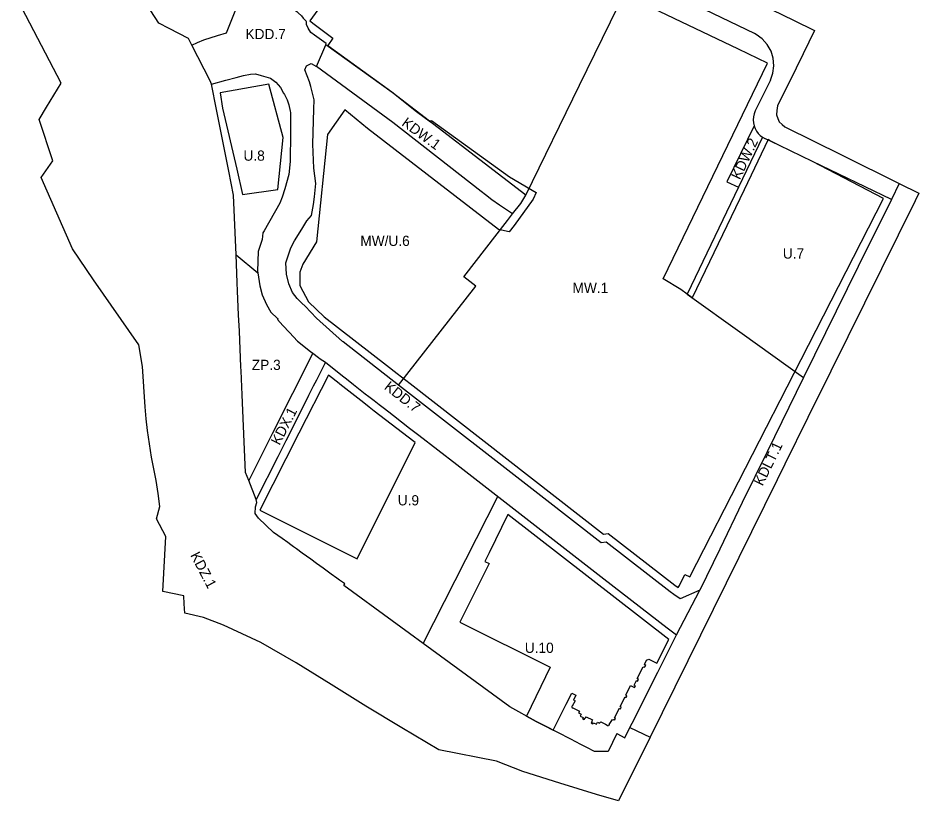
# Model space of a CAD drawing. Extents: x 7424029 to 7425690, y 5548509 to 5549459.
# Drawn here: x 7424711.6 to 7425151.9, y 5548508.9 to 5548891.5 of the extents above; entities that cross this region are included whole.
import ezdxf

# ---------------------------------------------------------------- set-up
doc = ezdxf.new("R2010")
doc.units = 0
for name, color, linetype in [('LIN_Linia Zabudowy Nieprzekraczalna', 7, 'Continuous'), ('LIN_Linia Zabudowy Obowiazujaca', 7, 'Continuous'), ('LIN_Linie_Rozgraniczajace', 7, 'Continuous'), ('TXT_oznaczenia_przeznaczen', 7, 'Continuous')]:
    doc.layers.add(name, color=color, linetype=linetype)

msp = doc.modelspace()

# ---------------------------------------------------------------- linework, layer by layer
at = {"layer": 'LIN_Linia Zabudowy Nieprzekraczalna'}
for p, q in [((7424865.54, 5548881.7), (7424862.95, 5548878.1)), ((7424834.13, 5548859.18), (7424810.38, 5548854.97)), ((7424841.17, 5548833.21), (7424834.13, 5548859.18)), ((7424871.36, 5548846.67), (7424862.85, 5548834.63)), ((7424838.56, 5548807.66), (7424841.17, 5548833.21)), ((7424862.85, 5548834.63), (7424857.5, 5548782.14)), ((7424821.24, 5548805.23), (7424838.56, 5548807.66)), ((7424829.77, 5548650.99), (7424877.39, 5548627.21)), ((7424927.49, 5548596.21), (7424971.61, 5548574.28)), ((7425023.83, 5548576.17), (7425029.71, 5548587.78)), ((7424971.61, 5548574.28), (7424960.06, 5548550.34)), ((7424973.12, 5548543.45), (7424979.54, 5548556.16)), ((7425006.03, 5548541.04), (7425006.03, 5548541.04))]:
    msp.add_line(p, q, dxfattribs=at)
for points in [[(7424926.28, 5548943.21), (7424912, 5548950), (7424898.58, 5548956.55), (7424887.87, 5548961.58), (7424879.12, 5548943.66), (7424883.08, 5548941.73), (7424880.88, 5548937.23), (7424886.34, 5548934.57), (7424866.76, 5548907.56), (7424854.3, 5548890.24)], [(7425077.86, 5548869.45), (7425063.65, 5548876.28), (7425018.21, 5548897.91), (7425017.6, 5548898.24), (7424999.04, 5548907.81), (7424993.69, 5548910.42), (7424976.65, 5548918.72), (7424971.24, 5548921.36), (7424954.74, 5548929.34), (7424949.38, 5548931.95), (7424931.72, 5548940.56), (7424926.28, 5548943.21)], [(7424854.3, 5548890.24), (7424856.99, 5548888.07), (7424865.54, 5548881.7)], [(7424862.95, 5548878.1), (7424894.37, 5548855.5), (7424906.4, 5548845.93), (7424913.17, 5548840.75), (7424913.69, 5548841.47), (7424951.87, 5548813.97), (7424964.88, 5548806.22)], [(7425026.91, 5548764.07), (7425077.86, 5548869.45)], [(7424810.38, 5548854.97), (7424811.62, 5548847.45), (7424818.53, 5548817.61), (7424821.24, 5548805.23)], [(7424951.66, 5548787.1), (7424946.48, 5548788.24), (7424882.45, 5548837.55), (7424871.36, 5548846.67)], [(7425078.22, 5548832.19), (7425066.4, 5548807.61), (7425041.05, 5548754.83)], [(7425134.61, 5548803.32), (7425099.89, 5548821.46), (7425083.71, 5548829.24), (7425078.79, 5548831.68), (7425078.22, 5548832.19)], [(7424964.88, 5548806.22), (7424963.31, 5548802.97), (7424954.08, 5548790.21)], [(7425094.36, 5548724.66), (7425134.61, 5548803.32)], [(7424954.08, 5548790.21), (7424951.66, 5548787.1)], [(7424857.5, 5548782.14), (7424850.76, 5548771.18), (7424849.29, 5548767.37), (7424849.29, 5548760.89), (7424853.5, 5548752.77), (7424861.29, 5548745.48)], [(7425041.05, 5548754.83), (7425038.58, 5548756.61), (7425035.46, 5548758.85), (7425026.91, 5548764.07)], [(7424861.29, 5548745.48), (7424891.62, 5548721.85), (7424896.89, 5548717.74), (7424903.21, 5548712.83)], [(7425034.23, 5548613.25), (7425034.83, 5548614.21), (7425037.49, 5548619.61), (7425039.98, 5548618.42), (7425094.36, 5548724.66)], [(7424863.35, 5548716.97), (7424848.89, 5548688.62), (7424829.77, 5548650.99)], [(7424905.62, 5548684.06), (7424904.99, 5548684.55), (7424885.72, 5548699.46), (7424883.25, 5548701.37), (7424880.64, 5548703.4), (7424868.84, 5548712.66), (7424868.51, 5548712.92), (7424863.35, 5548716.97)], [(7424903.21, 5548712.83), (7424997.69, 5548639.24)], [(7424877.39, 5548627.21), (7424905.62, 5548684.06)], [(7424950.95, 5548648.89), (7424941.81, 5548630.17), (7424939.72, 5548625.95), (7424941.93, 5548624.92), (7424927.49, 5548596.21)], [(7425029.71, 5548587.78), (7424950.95, 5548648.89)], [(7424997.69, 5548639.24), (7425000.07, 5548639.66), (7425032.6, 5548614.32), (7425034.23, 5548613.25)], [(7424960.06, 5548550.34), (7424964.84, 5548547.66), (7424968.71, 5548545.72), (7424969.04, 5548545.55), (7424973.12, 5548543.45)]]:
    msp.add_lwpolyline(points, dxfattribs=at)
at = {"layer": 'LIN_Linia Zabudowy Obowiazujaca'}
msp.add_lwpolyline([(7424979.54, 5548556.16), (7424982.24, 5548561.51), (7424984.2, 5548560.55), (7424983.01, 5548558.17), (7424983.83, 5548557.81), (7424982.4, 5548555.23), (7424982.15, 5548555.12), (7424982.44, 5548554.31), (7424982.67, 5548554.46), (7424985.96, 5548552.7), (7424985.56, 5548551.89), (7424986.74, 5548551.33), (7424986.26, 5548550.36), (7424987.78, 5548549.61), (7424987.53, 5548549.11), (7424988.36, 5548548.71), (7424988.6, 5548549.21), (7424988.75, 5548549.52), (7424988.91, 5548549.44), (7424989.19, 5548550.04), (7424992.31, 5548548.46), (7424992.02, 5548547.88), (7424992.11, 5548547.83), (7424991.97, 5548547.56), (7424991.72, 5548547.08), (7424992.58, 5548546.63), (7424992.8, 5548547.14), (7424994.35, 5548546.39), (7424994.8, 5548547.38), (7424995.86, 5548546.87), (7424996.37, 5548547.62), (7424998.69, 5548546.46), (7424999.57, 5548545.88), (7424999.81, 5548545.65), (7425000.67, 5548545.94), (7425000.58, 5548546.2), (7425002.16, 5548548.73), (7425002.58, 5548548.5), (7425002.75, 5548548.81), (7425003.23, 5548548.54), (7425003.64, 5548549.27), (7425003.13, 5548549.55), (7425005.5, 5548554.2), (7425006, 5548553.95), (7425006.4, 5548554.76), (7425005.94, 5548555.05), (7425008.26, 5548559.77), (7425008.73, 5548559.49), (7425009.12, 5548560.26), (7425008.68, 5548560.51), (7425010.93, 5548565.26), (7425012.87, 5548564.29), (7425013.31, 5548565.15), (7425012.76, 5548565.47), (7425013.78, 5548567.73), (7425014.31, 5548567.45), (7425014.83, 5548568.3), (7425014.21, 5548568.66), (7425017.19, 5548574.51), (7425017.82, 5548574.22), (7425018.36, 5548575.16), (7425017.73, 5548575.52), (7425018.8, 5548577.69), (7425019.92, 5548578.15), (7425023.83, 5548576.17)], dxfattribs=at)
at = {"layer": 'LIN_Linie_Rozgraniczajace'}
for p, q in [((7425071.5, 5548883.9), (7424965.29, 5548935.88)), ((7424818.18, 5548775.87), (7424828.75, 5548766.93)), ((7424909.58, 5548585.87), (7424946.07, 5548657.74))]:
    msp.add_line(p, q, dxfattribs=at)
for points in [[(7424959.86, 5548805.03), (7424985.93, 5548858.79), (7425012.35, 5548912.85)], [(7424819.44, 5548746.55), (7424818.95, 5548758), (7424818.76, 5548762.32), (7424818.18, 5548775.87), (7424816.93, 5548804.9), (7424814.63, 5548816.74), (7424808.68, 5548846.87), (7424806.23, 5548859.23), (7424805.46, 5548860.77), (7424796.61, 5548878.35), (7424794.97, 5548881.59), (7424785.5, 5548886.41), (7424780.39, 5548889.01), (7424766.28, 5548910.94)], [(7424796.61, 5548878.35), (7424799.36, 5548879.5), (7424802.4, 5548880.88), (7424809.16, 5548882.92), (7424813.57, 5548884.37), (7424818.11, 5548895.73), (7424820.27, 5548897.53), (7424827.62, 5548903.65), (7424828.52, 5548904.4), (7424834.41, 5548899.76), (7424838.27, 5548898.38), (7424841.16, 5548898.06)], [(7425080.11, 5548895.61), (7425090.51, 5548890.52), (7425100.91, 5548885.43), (7425095.36, 5548873.96), (7425091.91, 5548866.98), (7425082.81, 5548848.6), (7425082.5, 5548846.42), (7425082.2, 5548844.23), (7425082.9, 5548842.5), (7425083.6, 5548840.78), (7425085, 5548839.55), (7425086.39, 5548838.32), (7425114.33, 5548824.46), (7425142.26, 5548810.6), (7425142.26, 5548810.6), (7425151.9, 5548805.87), (7425150.1, 5548802.23), (7425108.82, 5548718.93), (7425097.58, 5548696.22), (7425086.34, 5548673.51), (7425082.67, 5548665.76), (7425026.38, 5548551.88), (7425020.52, 5548540.03), (7425005.11, 5548508.86), (7424994.38, 5548512.01), (7424976.33, 5548517.62), (7424958.29, 5548523.24), (7424945.44, 5548528.38), (7424917.23, 5548533.86), (7424899.11, 5548544.66), (7424881.67, 5548555.14), (7424864.63, 5548565.87), (7424847.59, 5548576.35), (7424830.29, 5548586.25), (7424812.11, 5548594.86), (7424802.26, 5548598.56), (7424793.07, 5548600.59), (7424792.82, 5548605.25), (7424792.62, 5548609.16), (7424782.4, 5548611.24), (7424783.88, 5548638.2), (7424779.32, 5548646.77), (7424781, 5548652.85), (7424780.03, 5548659.16), (7424779.05, 5548665.47), (7424777.94, 5548671.19), (7424776.83, 5548676.9), (7424775.83, 5548683.41), (7424774.83, 5548689.92), (7424774.29, 5548695.69), (7424773.75, 5548701.46), (7424772.48, 5548721.15), (7424770.69, 5548731.78), (7424748.53, 5548763.61), (7424738.23, 5548778.81), (7424730.6, 5548796.2), (7424722.97, 5548813.58), (7424728.61, 5548821.69), (7424721.93, 5548842.01), (7424725.59, 5548848.01), (7424732.74, 5548859.73), (7424711.62, 5548900.02)], [(7424841.16, 5548898.06), (7424842.27, 5548897.94), (7424843.78, 5548897.25), (7424845.62, 5548896.34), (7424847.88, 5548894.68), (7424848.59, 5548894), (7424850.08, 5548892.57), (7424850.97, 5548891.54)], [(7424856.53, 5548883.22), (7424854.73, 5548884.51), (7424853.43, 5548886.64), (7424852.66, 5548888.41), (7424852.56, 5548889.71), (7424852.36, 5548889.94), (7424850.97, 5548891.54)], [(7425044.81, 5548611.84), (7425035.13, 5548607.7), (7425032.18, 5548609.81), (7425030.27, 5548611.07), (7424999.02, 5548635.41), (7424996.63, 5548634.99), (7424968.59, 5548656.83), (7424897.59, 5548712.13), (7424870.54, 5548733.21), (7424870.15, 5548733.51), (7424857.41, 5548744.82), (7424851.87, 5548750.66), (7424850.36, 5548752.19), (7424848.09, 5548754.48), (7424845.82, 5548757.31), (7424844, 5548761.65), (7424842.77, 5548766.41), (7424842.45, 5548771.87), (7424844.99, 5548779.22), (7424846.73, 5548782.64), (7424848.63, 5548785.67), (7424850.88, 5548789.13), (7424852.71, 5548792.4), (7424854.99, 5548795.04), (7424855.97, 5548800.44), (7424856.49, 5548804.15), (7424857.15, 5548810.62), (7424856.17, 5548818.21), (7424855.73, 5548829.95), (7424856.19, 5548847), (7424856.31, 5548851.55), (7424854.79, 5548858.13), (7424854.06, 5548860.29), (7424851.84, 5548866.2), (7424852.66, 5548868.17), (7424854.83, 5548869.36), (7424857.41, 5548867.89), (7424862, 5548878.44), (7424862.27, 5548879.08), (7424856.53, 5548883.22)], [(7425079.28, 5548861.11), (7425080.54, 5548864.57), (7425081.02, 5548868.22), (7425080.71, 5548871.89), (7425079.62, 5548875.41), (7425077.79, 5548878.61), (7425075.32, 5548881.34), (7425072.32, 5548883.47), (7425071.5, 5548883.9)], [(7424953.33, 5548795.76), (7424957.34, 5548800.91), (7424959.86, 5548805.03), (7424894.38, 5548855.12), (7424862, 5548878.44)], [(7424897.59, 5548712.13), (7424935.32, 5548760.56), (7424929.48, 5548765.11), (7424950.88, 5548792.61), (7424953.33, 5548795.76), (7424950.26, 5548797.78), (7424946.85, 5548800.11), (7424943.18, 5548802.75), (7424940.03, 5548805.14), (7424937.98, 5548806.73), (7424894.76, 5548840.41), (7424887.49, 5548845.9), (7424857.41, 5548867.89)], [(7424806.23, 5548859.23), (7424813.11, 5548861.18), (7424818.18, 5548862.51), (7424821.76, 5548863.49), (7424825.3, 5548864.12), (7424827.67, 5548864.22), (7424830.48, 5548863.4), (7424835.03, 5548862.13), (7424837.6, 5548860.26), (7424839.91, 5548857.56), (7424841.35, 5548854.89), (7424841.77, 5548854.11), (7424843.12, 5548851.61), (7424844, 5548849.05), (7424844.68, 5548846.02), (7424844.76, 5548845.41), (7424844.71, 5548836.35), (7424844.7, 5548835.44), (7424844.62, 5548821.48), (7424843.94, 5548815.13), (7424842.06, 5548808.05), (7424840.76, 5548804.06), (7424839.58, 5548801.04), (7424831.86, 5548787.51), (7424831.27, 5548786.48), (7424830.85, 5548783.26), (7424828.9, 5548777.41), (7424828.59, 5548767.82), (7424828.75, 5548766.93)], [(7425079.28, 5548861.11), (7425071.89, 5548846.13), (7425071.32, 5548844.73), (7425070.98, 5548843.26), (7425070.86, 5548841.75), (7425070.96, 5548840.24), (7425071.3, 5548838.77), (7425071.8, 5548837.47), (7425072.48, 5548836.25), (7425073.32, 5548835.13), (7425074.31, 5548834.15), (7425075.43, 5548833.31), (7425076.52, 5548832.7)], [(7425071.3, 5548838.77), (7425058, 5548811.48), (7425063.7, 5548808.91)], [(7425075.43, 5548833.31), (7425063.7, 5548808.91), (7425038.58, 5548756.61), (7425065.46, 5548737.3), (7425095.42, 5548715.78)], [(7425138.47, 5548802.91), (7425099.9, 5548821.46), (7425083.73, 5548829.27), (7425076.52, 5548832.7)], [(7425142.26, 5548810.6), (7425138.47, 5548802.91), (7425122.22, 5548770.04), (7425095.42, 5548715.78), (7425077.74, 5548679.56), (7425065.56, 5548654.75), (7425054.51, 5548632.01), (7425044.81, 5548611.84)], [(7424828.75, 5548766.93), (7424829.86, 5548760.59), (7424830.98, 5548756.22), (7424833, 5548751.51), (7424835.17, 5548747.72), (7424838.41, 5548744.76), (7424838.69, 5548744.51), (7424838.47, 5548744.22)], [(7425004.19, 5548541.8), (7425000.04, 5548533.07), (7424993.29, 5548533.05), (7424989.53, 5548534.99), (7424986.66, 5548536.47), (7424981.73, 5548539.01), (7424969.04, 5548545.55), (7424968.71, 5548545.72), (7424964.84, 5548547.66), (7424952.02, 5548554.84), (7424918.13, 5548579.62), (7424870.9, 5548614.15), (7424871.31, 5548614.98), (7424871.15, 5548615.09), (7424870.14, 5548615.82), (7424868.74, 5548616.83), (7424867.34, 5548617.84), (7424864.7, 5548619.77), (7424860.69, 5548622.67), (7424859.11, 5548623.81), (7424857.54, 5548624.95), (7424854.73, 5548626.99), (7424850.51, 5548630.04), (7424847.7, 5548632.07), (7424846.29, 5548633.09), (7424844.87, 5548634.1), (7424843.47, 5548635.12), (7424840.68, 5548637.13), (7424836.49, 5548640.15), (7424829.13, 5548647.13), (7424828.29, 5548648.23), (7424827.44, 5548649.32), (7424827.62, 5548652.69), (7424828.31, 5548654.83), (7424828.06, 5548656.23), (7424824.34, 5548665.51), (7424822.78, 5548669.39), (7424822.13, 5548684.41), (7424821.14, 5548707.42), (7424820.63, 5548719.13), (7424820.55, 5548721.05), (7424819.79, 5548738.57), (7424819.44, 5548746.55)], [(7424838.47, 5548744.22), (7424841.1, 5548741.32), (7424844.29, 5548737.79), (7424848.15, 5548733.52), (7424854.56, 5548728.55), (7424855.64, 5548727.71), (7424858.43, 5548725.56), (7424859.24, 5548724.93), (7424861.8, 5548723.27), (7424870.98, 5548716.07), (7424871.31, 5548715.8), (7424875.59, 5548712.44), (7424881.34, 5548707.93), (7424883.1, 5548706.55), (7424885.7, 5548704.54), (7424888.17, 5548702.63), (7424890.11, 5548701.12), (7424892.78, 5548699.06), (7424895.1, 5548697.26), (7424902.99, 5548691.15), (7424907.44, 5548687.71), (7424926.05, 5548673.31), (7424975.87, 5548634.57), (7424997.96, 5548617.48), (7425028.81, 5548593.54), (7425033.39, 5548589.99), (7425044.81, 5548611.84)], [(7424855.64, 5548727.71), (7424835.84, 5548688.3), (7424824.34, 5548665.51)], [(7424861.8, 5548723.27), (7424857.45, 5548714.61), (7424855.91, 5548711.54), (7424853.62, 5548706.98), (7424850.58, 5548700.94), (7424842.53, 5548684.93), (7424838.58, 5548677.06), (7424828.06, 5548656.23)], [(7425004.19, 5548541.8), (7425008.15, 5548539.72), (7425010.62, 5548544.77), (7425011.68, 5548546.92), (7425015.32, 5548553.87), (7425019.78, 5548562.82), (7425024.23, 5548571.77), (7425026.71, 5548576.7), (7425033.39, 5548589.99)], [(7425010.62, 5548544.77), (7425020.52, 5548540.03)]]:
    msp.add_lwpolyline(points, dxfattribs=at)

# ---------------------------------------------------------------- texts
at = {"layer": 'TXT_oznaczenia_przeznaczen'}
for s, p in [('KDD.7', (7424822.78, 5548881.21)), ('U.8', (7424821.8, 5548821.8)), ('MW/U.6', (7424878.9, 5548780.14)), ('U.7', (7425085.37, 5548773.95)), ('MW.1', (7424982.61, 5548757.15)), ('ZP.3', (7424825.87, 5548719.51)), ('U.9', (7424897.2, 5548653.34)), ('U.10', (7424959.28, 5548581.24))]:
    msp.add_text(s, height=5, dxfattribs=at).set_placement(p)
for s, rotation, p in [('KDW.1', 323.8042, (7424898.73, 5548839.31)), ('KDW.2', 64.7096, (7425064.39, 5548812.16)), ('KDD.7', 321.8922, (7424890.2, 5548710.48)), ('KDX.1', 62.9624, (7424839.41, 5548682.39)), ('KDLT.1', 63.9072, (7425075.45, 5548662.49)), ('KDZ.1', 297.6791, (7424795.66, 5548629))]:
    msp.add_text(s, height=5, rotation=rotation, dxfattribs=at).set_placement(p)

doc.saveas('drawing.dxf')
